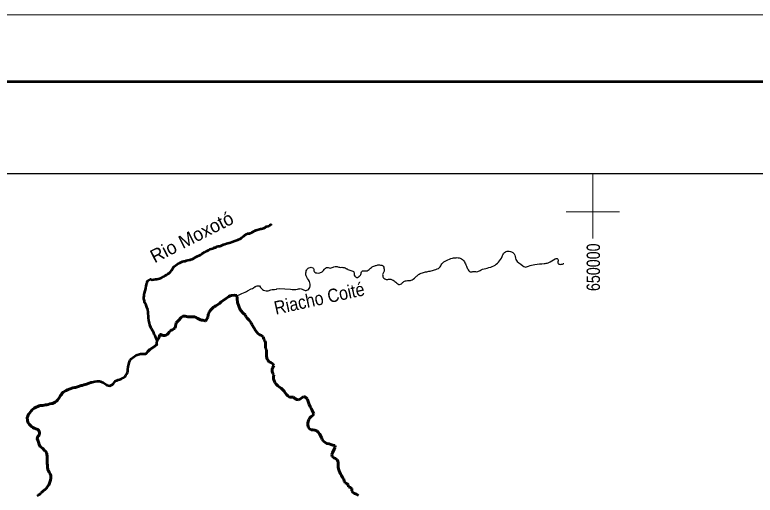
# Model space of a CAD drawing. Extents: x 553962 to 842807, y 8883888 to 9032388.
# Drawn here: x 628336 to 656083, y 9014382 to 9032388 of the extents above; entities that cross this region are included whole.
import ezdxf
from ezdxf.enums import TextEntityAlignment as Align

# ---------------------------------------------------------------- set-up
doc = ezdxf.new("R2010")
doc.units = 0
doc.header["$LTSCALE"] = 200
doc.linetypes.add('LONG_DASH_SHORT_DASH', pattern=[9.9, 6, -1.2, 1.5, -1.2])
for name, color, linetype, lineweight in [('2', 7, 'Continuous', 13), ('24', 7, 'Continuous', 25), ('3', 7, 'Continuous', 13), ('7', 7, 'Continuous', 90)]:
    doc.layers.add(name, color=color, linetype=linetype, lineweight=lineweight)
doc.layers.add('47', color=7, linetype='Continuous')
doc.layers.add('49', color=7, linetype='Continuous')

msp = doc.modelspace()

# ---------------------------------------------------------------- linework, layer by layer
at = {"layer": '2'}
for p, q in [((650000, 9024000), (650000, 9026438.8)), ((649000, 9025000), (651000, 9025000))]:
    msp.add_line(p, q, dxfattribs=at)
at = {"layer": '24', "lineweight": 53}
for points in [[(633413.9, 9022478.1), (633421.2, 9022477.1), (633480.4, 9022458.5), (633606.6, 9022474.9), (633658.1, 9022477.9), (633711.2, 9022491.3), (633762.6, 9022500.8), (633814.1, 9022520.8), (633917, 9022578.5), (633968.6, 9022613.4), (634020, 9022642.8), (634070.1, 9022674), (634114.4, 9022705.1), (634164.6, 9022749.5), (634211.6, 9022799.5), (634275.4, 9022905.1), (634276.2, 9022912.6), (634313.5, 9022956), (634360.5, 9022996.6), (634407, 9023028.7), (634463.3, 9023060.8), (634516.2, 9023093.9), (634619.2, 9023138.5), (634669.3, 9023151.8), (634720.7, 9023158.6), (634772.3, 9023177.5), (634823.9, 9023193.7), (634887.8, 9023203.3), (634902.5, 9023207.1), (634926.9, 9023210), (634978.4, 9023232.8), (635028.4, 9023251.7), (635132.8, 9023316), (635288.5, 9023394.6), (635338.7, 9023423), (635440.3, 9023486.3), (635485.1, 9023511.9), (635543.2, 9023541.2), (635595.9, 9023564.9), (635650.6, 9023598), (635699.1, 9023616), (635790.3, 9023636.1), (635793.1, 9023638), (635800.1, 9023649.3), (635819, 9023660.6), (635853.4, 9023668.3), (635876.7, 9023676.8), (635906.5, 9023697.6), (635956.5, 9023710), (636013.3, 9023718.7), (636059.5, 9023732.9), (636105.8, 9023750.9), (636162.5, 9023775.6), (636212.6, 9023793.6), (636275.1, 9023811.7), (636425, 9023859.2), (636478, 9023881.9), (636577.8, 9023919.9), (636690.9, 9023956), (636806.1, 9024008.1), (636823.2, 9024013.8), (636845.9, 9024034.6), (636912.2, 9024085.6), (636934.8, 9024108.2), (636956.3, 9024126.2), (637018.2, 9024171.5), (637057.1, 9024184.8), (637082.8, 9024185.8), (637104.5, 9024187.8), (637134.2, 9024195.4), (637161.3, 9024208.7), (637216.1, 9024229.5), (637230.8, 9024237.1), (637250.3, 9024253.2), (637273.6, 9024257.9), (637295.2, 9024272.1), (637314.4, 9024282.5), (637334, 9024298.6), (637359.5, 9024308.1), (637385.3, 9024320.4), (637537.2, 9024359.4), (637566.8, 9024363.3), (637618.3, 9024376.6), (637671, 9024396.6), (637718.9, 9024421.2), (637745.8, 9024437.2), (637770.3, 9024449.6), (637846.7, 9024469.6), (637851.3, 9024475.2), (637892.7, 9024501.7), (637913.2, 9024518.7), (637958, 9024544.2), (637971.9, 9024555.7)], [(633676.3, 9020181.4), (633676.3, 9020181.4), (633638.7, 9020264), (633612.2, 9020317.5), (633591.7, 9020369.2), (633563.5, 9020419.9), (633539.8, 9020471.5), (633453.9, 9020622.6), (633428.7, 9020672.4), (633401.8, 9020755.1), (633381.4, 9020829.3), (633365.3, 9020880), (633352.2, 9020933.6), (633345.6, 9021033.3), (633345, 9021086.9), (633332.3, 9021186.5), (633331.6, 9021241.1), (633318.4, 9021341.7), (633300.6, 9021397.1), (633254.7, 9021503.2), (633213.2, 9021588.7)], [(629274, 9017743.2), (629381.1, 9017748.3), (629434.5, 9017760.7), (629491.4, 9017765.6), (629537.5, 9017774.2), (629587.5, 9017786.6), (629642.2, 9017809.3), (629725.7, 9017821.8), (629743.8, 9017822.8), (629796.4, 9017840), (629846.5, 9017871.2), (629893.4, 9017902.3), (629935.3, 9017943.9), (629996.6, 9018037.2), (630048.9, 9018124.8), (630080.8, 9018160.6), (630113.1, 9018202.1), (630151.6, 9018240.8), (630254.2, 9018309.8), (630305.7, 9018332.6), (630507.3, 9018408.5), (630590.6, 9018415.3), (630611.9, 9018419.1), (630717.8, 9018458.1), (630816.3, 9018489.4), (630866, 9018499), (630920.7, 9018516.1), (630972.3, 9018535.1), (631025.1, 9018549.3), (631125.3, 9018586.4), (631186.5, 9018602.6), (631229.7, 9018616.8), (631281.3, 9018635.8), (631332.9, 9018645.4), (631418, 9018652.2), (631437.6, 9018655.1), (631504.9, 9018655.3), (631536.1, 9018652.6), (631547.1, 9018648.9), (631646.7, 9018604.1), (631758.6, 9018530.1), (631768.7, 9018519.8), (631780.5, 9018518), (631784.5, 9018507.7), (631788.3, 9018504.8), (631892.4, 9018481.7), (631899.2, 9018482.7), (631945.5, 9018503.5), (631993.7, 9018532.8), (632034.4, 9018569.6), (632106.5, 9018663.9), (632156.3, 9018682.9), (632209.2, 9018700), (632259.2, 9018719), (632312.1, 9018732.3), (632399.5, 9018775.8), (632439.6, 9018808.9), (632466.2, 9018835.3), (632501.5, 9018878.7), (632534.3, 9018936.2), (632553, 9018986.1), (632567.9, 9019034.1), (632569.1, 9019090.5), (632581.5, 9019191.2), (632619.5, 9019345.6), (632634.6, 9019396.4), (632664.3, 9019445.4), (632694.5, 9019486.9), (632744.2, 9019530.3), (632884.7, 9019635.2), (633050.2, 9019677.1), (633151.8, 9019677.4), (633222.6, 9019674.8), (633250.5, 9019683.4), (633294.8, 9019725.8), (633324, 9019767.3), (633357, 9019804.1), (633398.5, 9019840), (633496.1, 9019905.2), (633581.5, 9019968.5), (633647.8, 9020012.9), (633658.1, 9020043.1), (633663.7, 9020077.9), (633660.2, 9020090.1), (633676, 9020172.9), (633676.3, 9020181.4)], [(629194.7, 9016439.5), (629177.5, 9016494.9), (629187.5, 9016554.2), (629195.7, 9016563.6), (629200.5, 9016575.9), (629237.2, 9016624), (629245.2, 9016644.7), (629258.9, 9016658.8), (629261.5, 9016665.4), (629266.8, 9016705.9), (629260.6, 9016749.1), (629228.6, 9016818.6), (629200.8, 9016838.3), (629166.7, 9016852.3), (629065.4, 9016888.6), (629008.7, 9016922.3), (628959.7, 9016958.8), (628908.5, 9017002.8), (628868.8, 9017038.4), (628831.3, 9017088.2), (628817.9, 9017127.6), (628811.2, 9017173.7), (628801.7, 9017305.3), (628806.4, 9017311.9), (628840.5, 9017391), (628865.1, 9017422.1), (628888.6, 9017455.1), (628938, 9017517.3), (628963.8, 9017556), (628982.6, 9017573), (628987.4, 9017593.7), (629000, 9017599.4), (629064.4, 9017648.5), (629274, 9017743.2)], [(629174, 9014361), (629226.4, 9014394.1), (629271.5, 9014426.2), (629294, 9014445.1), (629316.4, 9014466.8), (629374.3, 9014513.1), (629388, 9014530), (629412.2, 9014553.6), (629427.9, 9014564), (629444.5, 9014579.1), (629470.7, 9014596.1), (629485.8, 9014608.4), (629530.1, 9014656.5), (629544.5, 9014677.3), (629557.5, 9014702.7), (629568.8, 9014719.7), (629611.6, 9014775.3), (629622.1, 9014794.1), (629637.4, 9014828), (629647.2, 9014866.6), (629660.2, 9014906.2), (629668.7, 9014940.1), (629681.7, 9015019.1), (629682.1, 9015052), (629684.7, 9015087.8), (629681.2, 9015117.8), (629661.9, 9015180.8), (629623.3, 9015244.6), (629598, 9015294.4), (629587.7, 9015308.5), (629574.6, 9015342.3), (629564.7, 9015437.2), (629564.2, 9015501.2), (629551.4, 9015566), (629550.9, 9015690.2), (629547.7, 9015731.5), (629550.5, 9015763.5), (629550.4, 9015794.6), (629544.2, 9015827.5), (629543.7, 9015859.4), (629537.5, 9015892.3), (629533.8, 9015933.7), (629524.4, 9015973.2), (629518.3, 9015976.9), (629516.5, 9015989.1), (629490.5, 9016027.6), (629451.9, 9016059.4), (629382.5, 9016129.8), (629285.4, 9016211.2), (629251.8, 9016287.3)], [(629251.8, 9016287.3), (629218.1, 9016364.3), (629194.7, 9016439.5)]]:
    msp.add_lwpolyline(points, dxfattribs=at)
at = {"layer": '24'}
for points in [[(636656.2, 9021865), (636684.9, 9021860.4), (636702.2, 9021873.6), (636740.9, 9021895.4), (636792.1, 9021921.9), (636838.7, 9021941.8), (636972.2, 9021990.2), (637015.9, 9022012), (637062.3, 9022041.3), (637193.3, 9022116), (637241.1, 9022134), (637284.8, 9022155.8), (637346, 9022200.2), (637368.3, 9022205), (637375.3, 9022213.5), (637379.5, 9022215.4), (637419.9, 9022224), (637504.2, 9022227.1), (637543.1, 9022171.7), (637575.9, 9022133.2), (637622.8, 9022093), (637661.8, 9022064.9), (637705.5, 9022049), (637750.8, 9022037), (637835.6, 9022037.2), (637934, 9022078.9), (637976.1, 9022088.5), (638019.7, 9022095.2), (638067.9, 9022095.4), (638139.8, 9022101.2), (638145.1, 9022104.1), (638157.6, 9022114.5), (638245.3, 9022132.2), (638672.6, 9022102.2)], [(636652.9, 9021868), (636641.6, 9021870.8), (636559.2, 9021880.9), (636454.2, 9021872.1), (636402.3, 9021849.3), (636354.6, 9021825.7), (636305.7, 9021795.4), (636263.9, 9021766.1), (636146.2, 9021677.3), (636105.2, 9021649), (636073, 9021625.4), (636004.2, 9021562.1), (635963.7, 9021536.6), (635867.3, 9021484.6), (635822.2, 9021456.2), (635780.5, 9021426.9), (635747.3, 9021396.7), (635692.5, 9021336.3), (635636.6, 9021264.7), (635616.1, 9021229.8), (635597.2, 9021191.2), (635584.4, 9021142.2), (635566, 9021043.4), (635559.6, 9021026.5), (635512, 9020943.6), (635480.4, 9020919), (635466.2, 9020917.1), (635380.8, 9020937.5), (635326.8, 9020945.8), (635298.1, 9020960.7), (635224.4, 9020989.6), (635174.2, 9021011.1), (635133.8, 9021040.1), (635075.6, 9021068.1), (634924.4, 9021068.6), (634868.1, 9021065.6), (634816.6, 9021072), (634714.8, 9021096.1), (634640.3, 9021095.8), (634633, 9021094.9), (634564.5, 9021042.9), (634472.5, 9020927.9), (634430.9, 9020895.8), (634394.5, 9020859), (634385.7, 9020847.7), (634383.8, 9020843), (634383.1, 9020829.8), (634371.1, 9020810.9), (634361.3, 9020698.1), (634352.5, 9020683), (634342.1, 9020680.1), (634329, 9020647.2), (634305.8, 9020635.8), (634240.7, 9020580.1), (634199.2, 9020572.4), (634144.7, 9020528.1), (634139.6, 9020509.2), (634131.3, 9020504.5), (634076.6, 9020431.9), (634046.6, 9020405.5), (633987.2, 9020367.7), (633978.5, 9020365.7), (633894.3, 9020363.6), (633891.4, 9020364.5), (633885.4, 9020372), (633871.8, 9020372.9), (633850.3, 9020386), (633845.5, 9020394.5), (633828.1, 9020398.2), (633817.3, 9020409.4), (633770.7, 9020403.6), (633766, 9020385.7), (633755.6, 9020376.3), (633753.8, 9020373.5), (633746.2, 9020297.3), (633676.3, 9020181.4)]]:
    msp.add_lwpolyline(points, dxfattribs=at)
for points in [[(646464.4, 9023111), (646597.9, 9023326), (646667.6, 9023459.6), (646783.8, 9023529.3), (646946.4, 9023506.1), (647045.1, 9023430.6), (647114.8, 9023215.6), (647376.1, 9022983.1), (647445.8, 9022936.6), (647585.1, 9022965.7), (647823.2, 9023029.6), (648171.7, 9023064.5), (648328.4, 9023093.5), (648589.8, 9023238.8), (648659.5, 9023250.4), (648694.3, 9023209.7), (648694.3, 9023064.5), (648758.2, 9023035.4), (648885.9, 9023058.7), (648910.6, 9023071.8)], [(638666.8, 9022105.1), (638926.3, 9022102.2), (638999.8, 9022122.2), (639130, 9022095.5), (639190.1, 9022065.4), (639313.6, 9022075.5), (639347, 9022095.5), (639387.1, 9022169), (639403.7, 9022285.9), (639377, 9022396.2), (639250.2, 9022610), (639250.2, 9022753.6), (639276.9, 9022830.4), (639360.3, 9022907.3), (639440.5, 9022924), (639537.3, 9022850.5), (639540.6, 9022797), (639654.1, 9022710.2), (639764.3, 9022720.2), (639877.8, 9022780.3), (639974.6, 9022897.2), (640074.8, 9022920.6), (640164.9, 9022893.9), (640295.1, 9022944), (640388.6, 9022957.4), (640502.1, 9022924), (640592.2, 9022924), (640749.2, 9022883.9), (640785.9, 9022860.5), (640815.9, 9022843.8), (640962.8, 9022797), (641029.6, 9022760.3), (641042.9, 9022740.2), (641059.6, 9022633.3), (641109.7, 9022563.2), (641136.4, 9022543.1), (641216.5, 9022566.5), (641253.3, 9022593.2), (641266.6, 9022610), (641293.3, 9022630), (641323.4, 9022750.3), (641363.4, 9022787), (641433.5, 9022793.7), (641493.6, 9022787), (641583.8, 9022813.7), (641697.3, 9022920.6), (641827.5, 9022977.4), (641937.7, 9023010.8), (642004.4, 9023010.8), (642084.6, 9022997.5), (642144.6, 9022967.4), (642168, 9022893.9), (642164.7, 9022750.3), (642121.3, 9022650), (642128, 9022589.9), (642134.6, 9022543.1), (642208.1, 9022493), (642248.1, 9022466.3), (642378.3, 9022483), (642481.8, 9022459.6), (642548.6, 9022416.2), (642685.5, 9022306), (642718.9, 9022282.6), (642795.7, 9022289.2), (642892.5, 9022369.4), (643002.6, 9022419.5), (643109.5, 9022426.2), (643223, 9022452.9), (643393.2, 9022586.6), (643486.7, 9022666.7), (643653.6, 9022733.6), (643810.5, 9022763.6), (643904, 9022783.7), (644067.6, 9022833.8), (644254.6, 9022910.6), (644338, 9023047.6), (644511.6, 9023177.9), (644735.3, 9023264.7), (644882.2, 9023284.8), (645025.8, 9023268.1), (645112.6, 9023218), (645202.7, 9023094.3), (645276.1, 9022927.3), (645349.6, 9022797), (645376.3, 9022760.3), (645506.5, 9022767), (645686.2, 9022762.3), (645814, 9022826.2), (646040.5, 9022896), (646290.2, 9022977.3), (646464.4, 9023111)]]:
    msp.add_spline(points, degree=3, dxfattribs=at)
at = {"layer": '24', "lineweight": 53}
msp.add_spline([(633213.2, 9021588.7), (633176.5, 9021739.5), (633198.3, 9021957.3), (633285, 9022315.7), (633329, 9022430.2), (633413.9, 9022478.1)], degree=3, dxfattribs=at)
at = {"layer": '3'}
msp.add_lwpolyline([(842807.3, 9032387.8), (842807.3, 8883887.8), (553961.7, 8883887.8), (553961.7, 9032387.8)], close=True, dxfattribs=at)
at = {"layer": '3', "lineweight": 53}
msp.add_lwpolyline([(840307.3, 9029887.8), (840307.3, 8886387.8), (560211.7, 8886387.8), (560211.7, 9029887.8)], close=True, dxfattribs=at)
at = {"layer": '3', "lineweight": 25}
msp.add_lwpolyline([(563033.9, 9026438.8), (793061.1, 9026438.8), (793495.6, 8889836.8), (563468.3, 8889836.8)], close=True, dxfattribs=at)
at = {"layer": '7', "linetype": 'LONG_DASH_SHORT_DASH', "lineweight": 60}
for points in [[(636652.9, 9021868), (636641.6, 9021870.8), (636559.2, 9021880.9), (636454.2, 9021872.1), (636402.3, 9021849.3), (636354.6, 9021825.7), (636305.7, 9021795.4), (636263.9, 9021766.1), (636146.2, 9021677.3), (636105.2, 9021649), (636073, 9021625.4), (636004.2, 9021562.1), (635963.7, 9021536.6), (635867.3, 9021484.6), (635822.2, 9021456.2), (635780.5, 9021426.9), (635747.3, 9021396.7), (635692.5, 9021336.3), (635636.6, 9021264.7), (635616.1, 9021229.8), (635597.2, 9021191.2), (635584.4, 9021142.2), (635566, 9021043.4), (635559.6, 9021026.5), (635512, 9020943.6), (635480.4, 9020919), (635466.2, 9020917.1), (635380.8, 9020937.5), (635326.8, 9020945.8), (635298.1, 9020960.7), (635224.4, 9020989.6), (635174.2, 9021011.1), (635133.8, 9021040.1), (635075.6, 9021068.1), (634924.4, 9021068.6), (634868.1, 9021065.6), (634816.6, 9021072), (634714.8, 9021096.1), (634640.3, 9021095.8), (634633, 9021094.9), (634564.5, 9021042.9), (634472.5, 9020927.9), (634430.9, 9020895.8), (634394.5, 9020859), (634385.7, 9020847.7), (634383.8, 9020843), (634383.1, 9020829.8), (634371.1, 9020810.9), (634361.3, 9020698.1), (634352.5, 9020683), (634342.1, 9020680.1), (634329, 9020647.2), (634305.8, 9020635.8), (634240.7, 9020580.1), (634199.2, 9020572.4), (634144.7, 9020528.1), (634139.6, 9020509.2), (634131.3, 9020504.5), (634076.6, 9020431.9), (634046.6, 9020405.5), (633987.2, 9020367.7), (633978.5, 9020365.7), (633894.3, 9020363.6), (633891.4, 9020364.5), (633885.4, 9020372), (633871.8, 9020372.9), (633850.3, 9020386), (633845.5, 9020394.5), (633828.1, 9020398.2), (633817.3, 9020409.4), (633770.7, 9020403.6), (633766, 9020385.7), (633755.6, 9020376.3), (633753.8, 9020373.5), (633746.2, 9020297.3), (633676.3, 9020181.4)], [(638704.2, 9018056.3), (638636.4, 9018051), (638565.9, 9018103.4), (638512.9, 9018158.4), (638467.5, 9018221), (638429.6, 9018278.6), (638384.1, 9018333.6), (638318.6, 9018391.1), (638250.6, 9018436), (638195.2, 9018478.4), (638127.1, 9018538.4), (638081.6, 9018601), (638030.9, 9018738.8), (638035.6, 9018816.7), (638045.4, 9018887), (638002.5, 9018942.1), (637984.6, 9019017.3), (637986.8, 9019100.2), (638006.7, 9019173), (638041.6, 9019238.5), (638006.2, 9019308.6), (637935.7, 9019353.5), (637870.2, 9019383.3), (637807.2, 9019450.8), (637784.3, 9019518.5), (637768.9, 9019603.8), (637768.4, 9019759.5), (637765.6, 9019827.2), (637732.7, 9019892.4), (637732.2, 9020033), (637726.9, 9020100.7), (637706.6, 9020170.9), (637671.2, 9020236), (637648.2, 9020316.3), (637577.7, 9020368.7), (637514.8, 9020396), (637454.3, 9020436), (637403.9, 9020488.5), (637355.9, 9020556), (637307.9, 9020643.7), (637216.9, 9020773.9), (637189.1, 9020836.5), (637151.2, 9020894.1), (637100.7, 9020954.1), (637042.7, 9021016.6), (636994.7, 9021076.7), (636964.3, 9021146.8), (636898.8, 9021209.3), (636797.8, 9021321.9), (636752.3, 9021397), (636734.5, 9021467.2), (636684.8, 9021608.7), (636652.9, 9021875.9)], [(633316.8, 9019757.1), (633324, 9019767.3), (633357, 9019804.1), (633398.5, 9019840), (633496.1, 9019905.2), (633581.5, 9019968.5), (633647.8, 9020012.9), (633658.1, 9020043.1)], [(629274, 9017743.2), (629381.1, 9017748.3), (629434.5, 9017760.7), (629491.4, 9017765.6), (629537.5, 9017774.2), (629587.5, 9017786.6), (629642.2, 9017809.3), (629725.7, 9017821.8), (629743.8, 9017822.8), (629796.4, 9017840), (629846.5, 9017871.2), (629893.4, 9017902.3), (629935.3, 9017943.9), (629996.6, 9018037.2), (630048.9, 9018124.8), (630080.8, 9018160.6), (630113.1, 9018202.1), (630151.6, 9018240.8), (630254.2, 9018309.8), (630305.7, 9018332.6), (630507.3, 9018408.5), (630590.6, 9018415.3), (630611.9, 9018419.1), (630717.8, 9018458.1), (630816.3, 9018489.4), (630866, 9018499), (630920.7, 9018516.1), (630972.3, 9018535.1), (631025.1, 9018549.3), (631125.3, 9018586.4), (631186.5, 9018602.6), (631213.4, 9018611.4)], [(639653.5, 9016800.1), (639585.6, 9016819.9), (639510.2, 9016829.6), (639439.8, 9016831.8), (639379.4, 9016866.7), (639339, 9016921.8), (639318.6, 9017007.1), (639315.8, 9017084.9), (639335.7, 9017150.2), (639360.6, 9017215.6), (639393, 9017276), (639445.6, 9017326.4), (639505.7, 9017374.4), (639538.1, 9017437.3), (639502.7, 9017502.4), (639469.8, 9017575.1), (639444.4, 9017645.2), (639401.5, 9017705.3), (639368.5, 9017778), (639348.2, 9017850.7), (639317.8, 9017925.9), (639297.4, 9017996.1), (639247, 9018043.6), (639169, 9018075.9), (639103.8, 9018040.5), (639046.1, 9017997.5), (638980.9, 9017962.1), (638900.5, 9017964.3), (638835.1, 9018006.7), (638779.6, 9018059.2), (638704.2, 9018056.3)], [(629194.7, 9016439.5), (629177.5, 9016494.9), (629187.5, 9016554.2), (629195.7, 9016563.6), (629200.5, 9016575.9), (629237.2, 9016624), (629245.2, 9016644.7), (629258.9, 9016658.8), (629261.5, 9016665.4), (629266.8, 9016705.9), (629260.6, 9016749.1), (629228.6, 9016818.6), (629200.8, 9016838.3), (629166.7, 9016852.3), (629065.4, 9016888.6), (629008.7, 9016922.3), (628959.7, 9016958.8), (628908.5, 9017002.8), (628868.8, 9017038.4), (628831.3, 9017088.2), (628817.9, 9017127.6), (628811.2, 9017173.7), (628801.7, 9017305.3), (628806.4, 9017311.9), (628840.5, 9017391), (628865.1, 9017422.1), (628888.6, 9017455.1), (628938, 9017517.3), (628963.8, 9017556), (628982.6, 9017573), (628987.4, 9017593.7), (629000, 9017599.4), (629064.4, 9017648.5), (629274, 9017743.2)], [(641210.1, 9014371.6), (641144.6, 9014416.5), (641071.7, 9014443.8), (641003.7, 9014483.7), (640965.8, 9014543.8), (640965.5, 9014626.6), (640912.5, 9014674.1), (640844.6, 9014691.4), (640824.2, 9014771.6), (640776.3, 9014821.6), (640713.4, 9014849), (640683, 9014911.6), (640660.2, 9014976.8), (640614.7, 9015039.3), (640579.2, 9015117), (640541.3, 9015177.1), (640508.4, 9015254.8), (640472.9, 9015332.5), (640455.1, 9015415.2), (640454.5, 9015560.8), (640451.7, 9015636.1), (640416.3, 9015703.8), (640355.8, 9015758.8), (640287.9, 9015781.1), (640227.4, 9015828.5), (640219.6, 9015903.8), (640236.9, 9015971.6), (640304.3, 9016102.5), (640336.7, 9016177.9), (640326.4, 9016245.7), (640251, 9016257.9), (640175.5, 9016277.7), (640112.6, 9016305), (640024.6, 9016322.2), (639961.7, 9016357.1), (639898.7, 9016409.5), (639855.7, 9016474.6), (639827.8, 9016547.3), (639754.4, 9016687.6), (639704, 9016747.6), (639653.5, 9016800.1)], [(629251.8, 9016287.3), (629218.1, 9016364.3), (629194.7, 9016439.5)], [(629568.8, 9014719.7), (629611.6, 9014775.3), (629622.1, 9014794.1), (629637.4, 9014828), (629647.2, 9014866.6), (629660.2, 9014906.2), (629668.7, 9014940.1), (629681.7, 9015019.1), (629682.1, 9015052), (629684.7, 9015087.8), (629681.2, 9015117.8), (629661.9, 9015180.8), (629623.3, 9015244.6), (629598, 9015294.4), (629587.7, 9015308.5), (629574.6, 9015342.3), (629564.7, 9015437.2), (629564.2, 9015501.2), (629551.4, 9015566), (629550.9, 9015690.2), (629547.7, 9015731.5), (629550.5, 9015763.5), (629550.4, 9015794.6), (629544.2, 9015827.5), (629543.7, 9015859.4), (629537.5, 9015892.3), (629533.8, 9015933.7), (629524.4, 9015973.2), (629518.3, 9015976.9), (629516.5, 9015989.1), (629490.5, 9016027.6), (629451.9, 9016059.4), (629382.5, 9016129.8), (629285.4, 9016211.2), (629251.8, 9016287.3)]]:
    msp.add_lwpolyline(points, dxfattribs=at)

# ---------------------------------------------------------------- texts
at = {"layer": '47', "width": 0.8}
msp.add_text('650000', height=500, rotation=90, dxfattribs=at).set_placement((650266, 9022925.4), align=Align.CENTER)
at = {"layer": '49'}
msp.add_text('Rio Moxotó', height=500, rotation=26.825, dxfattribs=at).set_placement((635080.7, 9023830.7), align=Align.CENTER)
at = {"layer": '49', "width": 0.9}
msp.add_text('Riacho Coité', height=500, rotation=12.335, dxfattribs=at).set_placement((639799.3, 9021513.7), align=Align.CENTER)

doc.saveas('drawing.dxf')
